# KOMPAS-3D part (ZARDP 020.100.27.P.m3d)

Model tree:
1. Плоскость XY
2. Плоскость ZX
3. Плоскость ZY
4. Ось X
5. Ось Y
6. Ось Z
7. Начало координат
8. Булева операция:1
9. Булева операция:2
10. Булева операция:3
11. Булева операция:4
